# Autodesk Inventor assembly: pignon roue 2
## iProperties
Author: Administrateur
Created: 2001-04
Part Number: pignon roue 2
Document SubType Name: Assemblage
Designer: Administrateur
Control State: 0
Master: False
Checked Out: False
PropertySet Name: Design Tracking Control
Shininess: 37.0
PropertySet Name: _Private Model Information
Length Units: 11269
Angle Units: 11283
Time Units: 11279
Mass Units: 11290
Length Display Precision: 3
Angle Display Precision: 2
Compacted: False
Density: 0.0
Volumn: 0.0
Area: 0.0
PropertySet Name: Model Information
